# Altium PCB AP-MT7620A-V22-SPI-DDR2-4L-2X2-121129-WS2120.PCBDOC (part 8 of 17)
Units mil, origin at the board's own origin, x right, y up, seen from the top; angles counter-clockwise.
Board outline 7316 x 4279 mil, 4 copper layers (Top, Inner Layer 2, Inner Layer 3, Bottom), stack 35.4 mil thick; 640 components, 473 nets, 2041 pads, 2358 vias.
Unrouted connection lines stored in the file: 11.
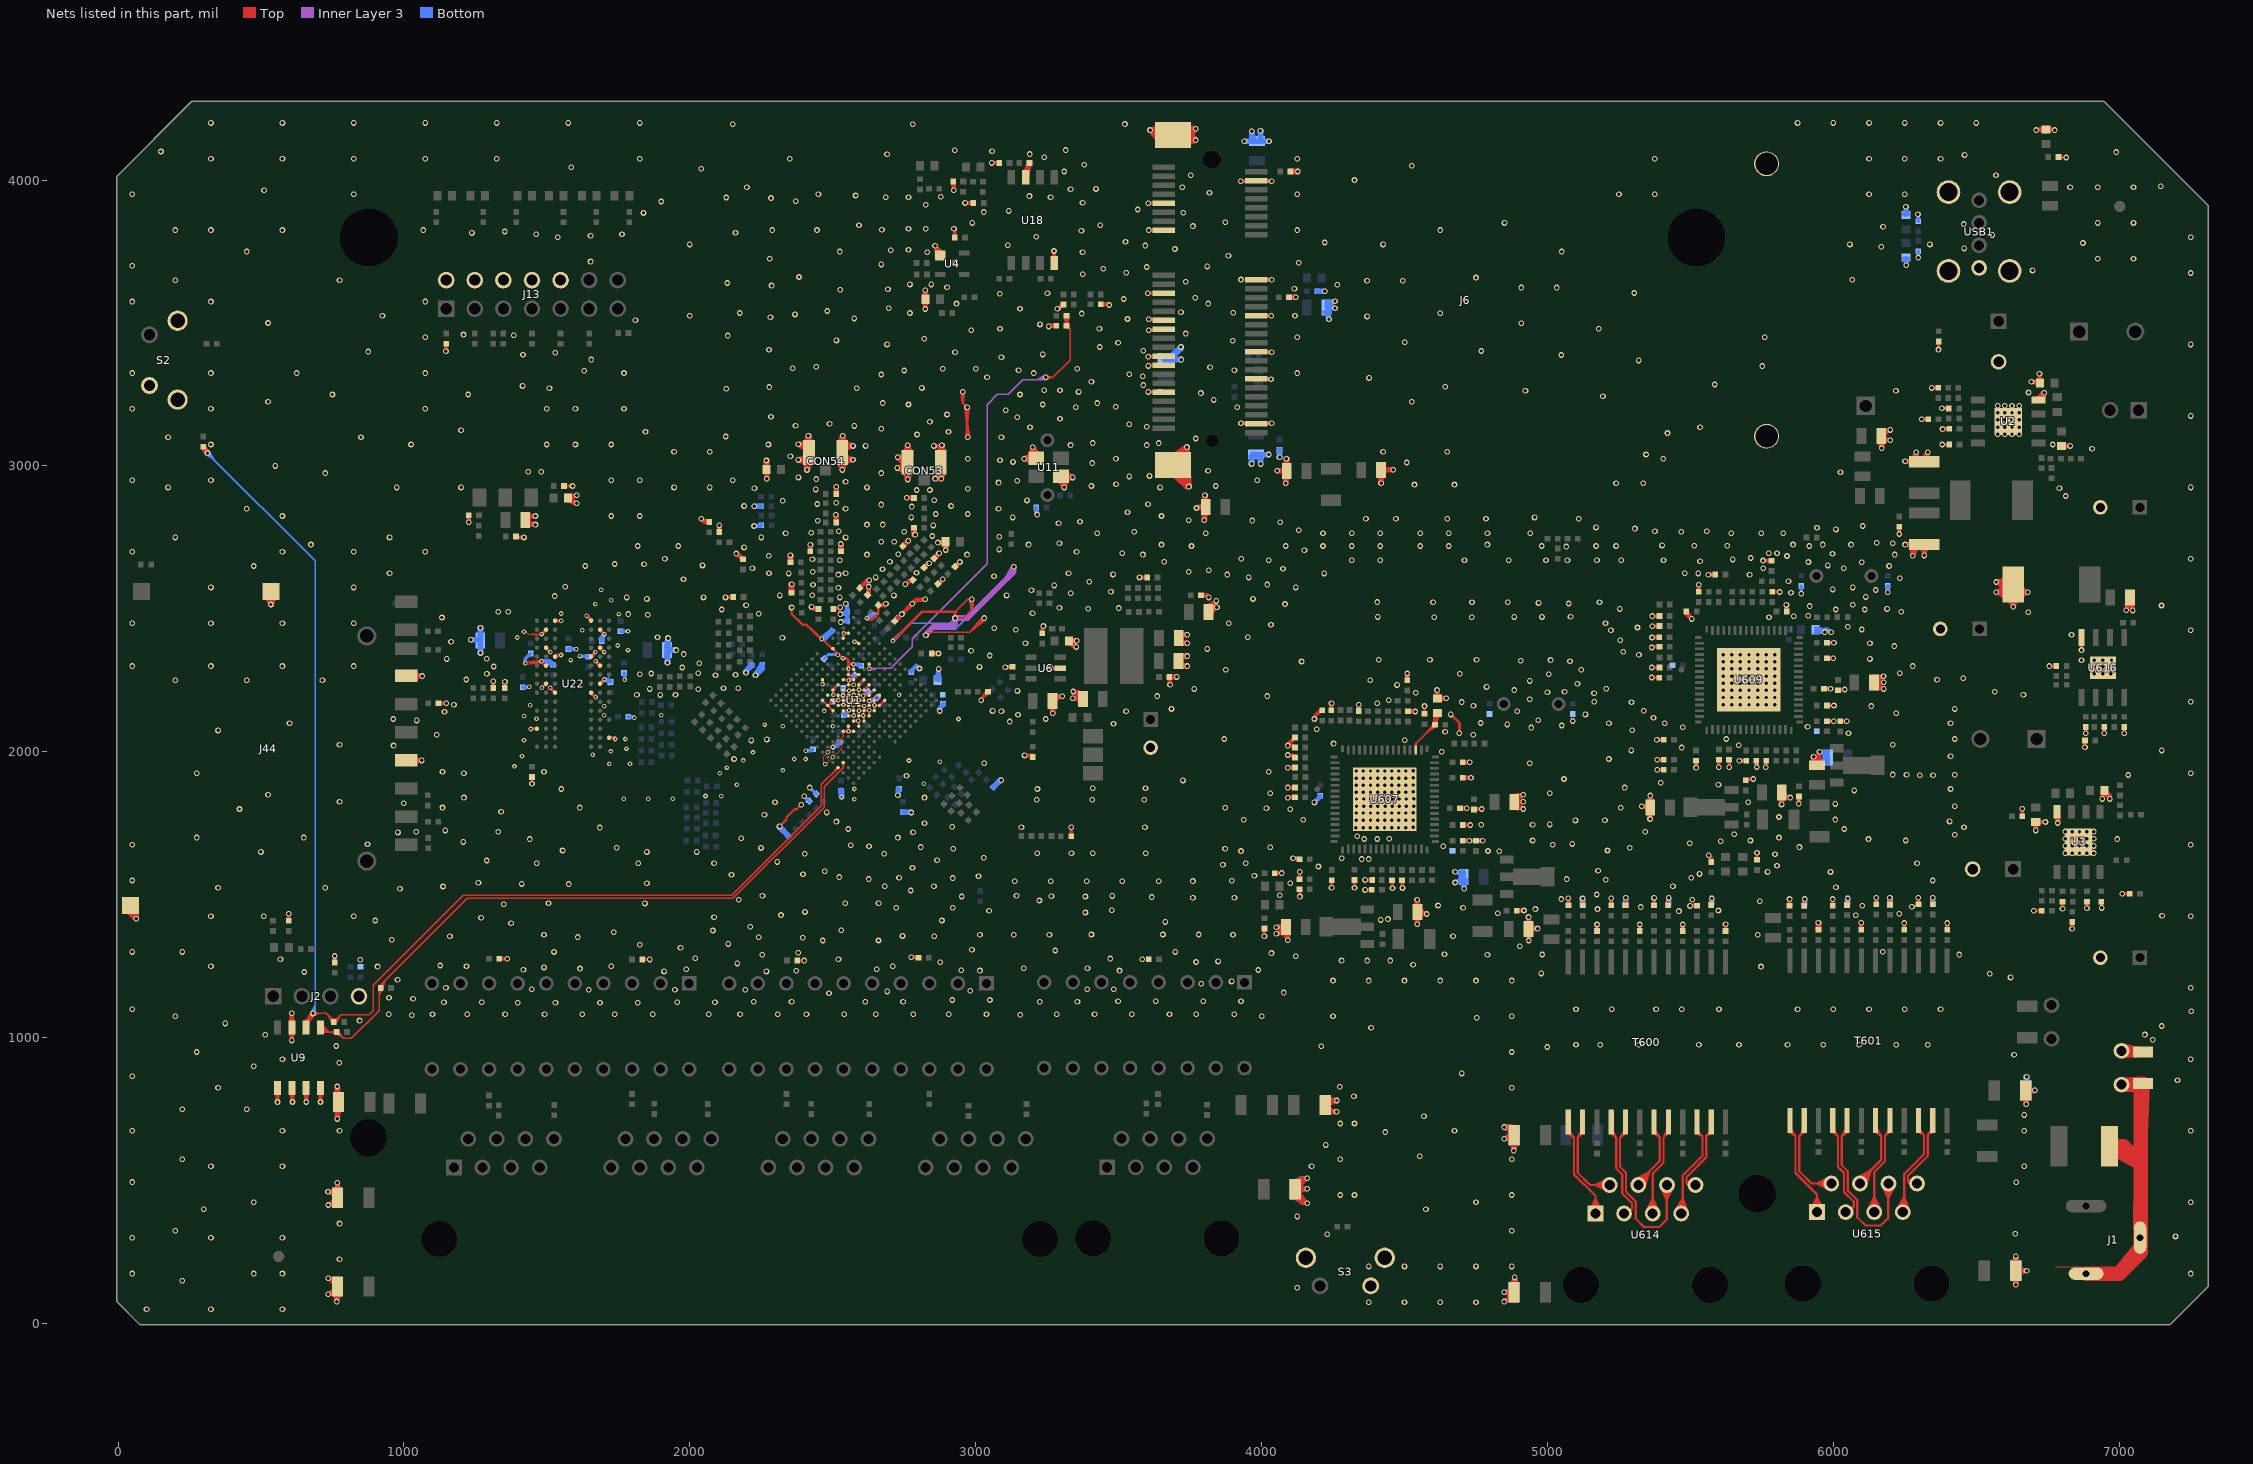
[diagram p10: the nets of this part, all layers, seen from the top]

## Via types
v1: diameter 20, hole 12, Top to Bottom, 2117 vias
v2: diameter 16, hole 8, Top to Bottom, 241 vias

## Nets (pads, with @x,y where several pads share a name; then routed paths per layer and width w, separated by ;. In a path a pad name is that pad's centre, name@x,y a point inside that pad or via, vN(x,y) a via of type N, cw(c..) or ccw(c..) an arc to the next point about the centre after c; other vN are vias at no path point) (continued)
GND: (continued)
  Inner Layer 3 w20: v1(2826,2408) 2824.14,2409.86 2854.28,2440 2920,2440 2928,2448 v1(2928,2468) 2971.59,2468 3111.59,2608 3112.1,2608 ; 3112.1,2608 3133,2628.9 v1(3133,2647) 3112.1,2608
  Bottom w5: v2@2706.28,2392.05 2754.61,2432.61 v2@2714.05,2384.28 ; v2(2710,2388) 2772,2450 2910,2450 v1(2928,2468) ; v1(2826,2408) 2846,2428 2928.14,2428 2986,2485.86 ; v1@2978.52,2533.42 2986,2485.86 ; v1@2993.48,2533.42 2986,2485.86 ; 2986,2485.86 v1(2986,2534) 2986,2485.86
  Bottom w8: C70.2@2531.04,2222.28 v2@2537,2198 ; C43.2@2535.44,2132.83 v2(2557,2145) ; v2(2536,2197) v2@2537,2198 ; C70.2@2537,2223 v2@2537,2198 ; C70.2@2542.96,2222.28 v2@2537,2198 ; C43.2@2543.62,2124.17 v2(2557,2145) ; v2(2555.5,2250.9) v2@2560.24,2250.9 ; C44.2@2571.39,2271.71 v2@2560.24,2250.9 ; C44.2@2580.12,2263.63 v2@2560.24,2250.9 ; v2(2557,2145) 2540,2128 C43.2@2539,2128 v2(2557,2145) ; v2@2560.24,2250.9 2576.27,2266.93 C44.2@2576.27,2268.23 v2@2560.24,2250.9
  Bottom w10: C75.2@2469.77,2325.23 2484.54,2340 v2(2518,2340) ; v2(2607,2196) 2608.26,2196 C40.2@2623.45,2211.19
  Bottom w12: C131.2@1416,2226 1436,2226 v2(1438,2228) ; v2(1425,2310) 1425,2325 C140.2@1444,2344 ; C138.2@1758,2422 v2(1784,2422) ; C132.2@1785,2123 1804,2123 v2(1806,2119) ; v2(2620,2468) v2@2620,2469 ; C36.2@2725.73,2466.73 2726.23,2466.23 v1(2742,2482) ; v1(2803.5,2291.5) 2792.19,2302.81 ; C42.2@2859.27,2254.17 v1(2871,2290) ; C42.2@2867.09,2250.5 2871,2250.5 v1(2871,2290) ; C42.2@2867.09,2252.5 v1(2871,2290) ; C42.2@2875.09,2252.52 v1(2871,2290) ; C118.1@4108.7,444.32 4142.5,421.7 ; C118.1@4113.51,498.63 v1(4160,508) ; C118.1@4118.12,454.25 4142.5,421.7 ; C118.1@4126.22,474.72 v1(4160,508) ; C118.1@4130.3,460.5 4142.5,421.7 ; v1(4160,421) 4159.3,421.7 4142.5,421.7 ; C229.2@4217.5,3539.3 v1(4236,3513) ; C229.2@4225.82,3576.88 v1(4257,3576) ; C229.2@4227.45,3544 v1(4236,3513) ; C229.2@4227.45,3566 v1(4257,3576) ; C229.2@4229.73,3544.24 v1@4254,3555 ; C229.2@4229.73,3565.76 v1@4254,3555 ; C229.2@4232.76,3556.37 v1(4257,3576) ; C229.2@4238.4,3545.07 v1(4236,3513) ; v1(4257,3552) v1@4254,3555 ; C797.2@4702.64,1561.9 v1(4677,1543) ; C797.2@4703.25,1563.92 v1(4677,1581) ; C797.2@4707.54,1552.05 v1(4677,1543) ; C797.2@4707.54,1563.05 C797.2@4708.27,1563.78 ; C797.2@4707.54,1574.05 v1(4677,1581) ; C797.2@4708.06,1585.04 v1(4677,1581) ; C797.2@4708.8,1541.12 v1(4677,1543) ; C810.1@4869.65,129.25 v1(4885.3,161.6) ; C817.1@4870.05,640.66 v1(4882.6,605.4) ; C810.1@4874.58,105.13 v1(4849,77) ; C817.1@4876.72,670.41 v1(4848.8,646.4) ; C810.1@4880.12,96.6 v1(4849,110) ; C810.1@4880.12,123.4 v1(4849,110) ; C810.1@4882.88,94.25 v1(4849,77) ; C810.1@4882.88,125.75 v1(4885.3,161.6) ; C817.1@4883.56,642.81 v1(4882.6,605.4) ; C817.1@4883.56,658.56 v1(4848.8,646.4) ; C817.1@4885.6,645.03 v1(4848.8,646.4) ; C810.1@4886.8,81.14 v1(4849,77) ; C810.1@4896.46,127.44 v1(4885.3,161.6) ; C817.1@4896.95,639.97 v1(4882.6,605.4) ; v1(5888,2553) C804.2@5888,2580 ; RC3.2@5937.1,2417.02 v1(5970,2419) ; RC3.2@5937.59,2425 v1(5970,2419) ; RC3.2@5938.65,2419.07 v1@5967.69,2427 ; RC3.2@5938.65,2434.93 v1@5967.69,2427 ; RC3.2@5939.99,2432.63 v1(5970,2419) ; C799.2@5976.82,1982.11 v1(5952,2000) ; C799.2@5981.54,1981.05 5981.54,1990.96 5972.5,2000 v1(5952,2000) ; C799.2@5981.54,1992.05 v1(5952,2000) ; C799.2@5982.44,2003.01 v1(5952,2000) ; v1(5992,2418) 5980.69,2429.31 5970,2429.31 v1@5967.69,2427 ; D3.1@6246.07,3878.68 v1(6254,3907) ; D4.1@6246.14,3726.9 v1(6255,3702) ; D3.1@6254,3877.59 v1(6254,3907) ; D4.1@6261.95,3727.5 v1(6255,3702) ; D3.1@6261.93,3878.68 v1(6254,3907) ; v1(6296,3880) 6297,3879 UC1.2@6297,3856 ; v1(6297,3729) UC2.2@6297,3751 ; C729.1@6624.71,203.49 v1@6638.12,234.88 ; C729.1@6624.73,166.43 v1@6638.12,136.12 ; C729.1@6638.12,169.25 v1@6638.12,136.12 ; C729.1@6638.12,200.75 v1@6638.12,234.88 ; C729.1@6640.59,171.54 v1(6676,185) ; C729.1@6640.59,198.46 v1(6676,185) ; C729.1@6651.51,166.43 v1@6638.12,136.12 ; C729.1@6651.53,203.49 v1@6638.12,234.88 ; v2@2620,2469 2629,2478 ; v2@2620,2469 C94.2@2645,2478 ; 2629,2478 C94.2@2645,2478 ; 2629,2478 C94.2@2645,2478 ; 2792.19,2302.81 2771.19,2281.81 2775,2281.81 C210.2@2775,2278 2792.19,2302.81 ; v1(3604,3259) v1@3605,3260 ; v1(3604,3259) C222.2@3645,3260 ; v1(3604,3259) C222.2@3645,3260 ; v1@3605,3260 C222.2@3645,3260 ; v1@3605,3260 C222.2@3645,3260 ; C118.1@4118.12,470 C118.1@4122.7,470 ; C118.1@4118.12,470 v1@4158.4,470 ; C118.1@4118.12,470 v1(4160,471.6) ; C118.1@4118.12,485.75 4134.4,508 ; C118.1@4118.12,485.75 v1(4160,508) ; C118.1@4118.12,485.75 4134.4,508 ; C118.1@4122.7,470 v1@4158.4,470 ; C118.1@4122.7,470 C118.1@4122.7,474.5 ; C118.1@4122.7,470 v1(4160,471.6) ; C118.1@4122.7,474.5 4122.7,441.5 4142.5,421.7 ; C118.1@4122.7,474.5 4122.7,496.3 4134.4,508 ; 4134.4,508 v1(4160,508) ; 4134.4,508 4109.42,496.32 4134.4,508 ; 4134.4,508 4130.82,480.66 4134.4,508 ; v1@4158.4,470 v1(4160,471.6) ; v1@4158.4,470 4120.44,483.49 v1(4160,471.6) ; v1@4158.4,470 4120.44,456.51 v1(4160,471.6) ; C229.2@4227.45,3555 4233.45,3549 4236,3549 v1(4236,3513) ; C229.2@4227.45,3555 v1@4254,3555 ; C229.2@4227.45,3555 4227,3555.45 4227,3567 4236,3576 v1(4257,3576) ; v1(4677,1543) 4705,1543 4705,1552.2 4705,1563 C797.2@4708.27,1563.78 ; v1(4677,1581) 4708.5,1581 4708.5,1564.01 C797.2@4708.27,1563.78 ; v1(4848.8,646.4) 4882.6,646.4 v1(4882.6,605.4) ; v1(4849,77) 4880.5,108.5 C810.1@4880.5,110 ; v1(4849,110) C810.1@4880.5,110 ; v1(4849,110) C810.1@4882.88,110 ; C810.1@4880.5,110 C810.1@4882.88,110 ; C810.1@4882.88,110 4885.3,112.42 v1(4885.3,161.6) ; v1@5967.69,2427 RC3.2@5937.59,2427 5937.59,2419 v1(5970,2419) ; v1(6255,3702) 6255,3727.41 D4.1@6254,3728.41 v1(6255,3702) ; v1@6638.12,136.12 C729.1@6638.12,185 ; v1@6638.12,136.12 v1(6638,136) C729.1@6638.12,185 ; C729.1@6638.12,185 v1(6676,185) ; C729.1@6638.12,185 v1@6638.12,234.88 ; C729.1@6638.12,185 v1(6676,185) ; C729.1@6638.12,185 v1(6638,235) v1@6638.12,234.88 ; v2(1615,2335) 1643,2335 C135.2@1645,2333 v2(1615,2335) ; C139.2@1770,2276 1772,2274 v2(1772,2252) C139.2@1770,2276 ; v1(2400,1845) C57.2@2417.27,1827.73 v1(2400,1845) ; v2(2406,2004) 2426,2004 C76.2@2431,2009 v2(2406,2004) ; v1(2420,1875) C58.2@2442.27,1852.73 v1(2420,1875) ; v2(2572.5,2306.5) 2594.2,2306.5 C91.2@2599.9,2300.8 v2(2572.5,2306.5)
  Bottom w15: C128.2@1576,2360 1602,2360 v2(1603,2359) ; v2(2500.5,2017) v2@2502.71,2014.79 ; v1(2528,2454) v1@2528,2457.52 ; v1(2546,2518) v1@2549.67,2518 ; v1(2728,1848) v1@2727.79,1848 ; v1(2874.16,2142.97) v1@2869.68,2147.45 ; C108.2@3212,2855 3212,2830 v1(3215,2830) ; C797.2@4698.21,1550.26 v1(4708.6,1521.4) ; C797.2@4705,1552.2 4708.6,1548.6 v1(4708.6,1521.4) ; C797.2@4707.54,1552.05 v1(4708.6,1521.4) ; C797.2@4716.97,1550.9 v1(4708.6,1521.4) ; v1(5931,1983) 5948.4,1965.6 ; C799.2@5978.95,1979.19 5948.4,1965.6 ; C799.2@5981.46,1960.55 5948.4,1965.6 ; C799.2@5981.54,1970.05 5948.4,1965.6 ; C799.2@5981.54,1990.96 C799.2@5981.54,1981.05 5981.54,1969.14 5978,1965.6 5948.4,1965.6 ; v1(6190,2558) C803.2@6190,2580 ; v2@2502.71,2014.79 2522.96,2035.04 2524,2035.04 C41.2@2524,2034 v2@2502.71,2014.79 ; v1@2528,2457.52 2550.9,2457.52 C103.2@2550.9,2458.7 ; v1@2528,2457.52 C103.2@2550.9,2458.7 ; v1@2549.67,2518 2549.67,2488.7 C97.2@2550.9,2488.7 ; v1@2549.67,2518 C97.2@2550.9,2488.7 ; C103.2@2550.9,2458.7 C97.2@2550.9,2488.7 ; C103.2@2550.9,2458.7 C97.2@2550.9,2488.7 ; C97.2@2550.9,2488.7 2544.2,2482 v1(2526,2482) C97.2@2550.9,2488.7 ; v1@2727.79,1848 2727.79,1871 C167.2@2733,1871 v1@2727.79,1848 ; v1@2869.68,2147.45 2888.11,2165.89 2888.11,2168 C69.1@2886,2168 v1@2869.68,2147.45 ; v2(1481,2317) 1510,2317 1521,2306 C133.2@1521,2305 v2(1481,2317) ; C130.2@1692,2388 1692,2400 v2(1701.5,2412) C130.2@1692,2388 ; v2(1700.5,2253) 1715,2253 1723,2245 C129.2@1723,2244 v2(1700.5,2253) ; v1(2225,2790) 2248,2790 R130.1@2250,2793 v1(2225,2790) ; v2(2628,2178) 2643.54,2178 C39.2@2655.27,2189.73 v2(2628,2178) ; v1(4185,1823) 4205,1843 C768.2@4205,1846 v1(4185,1823)
  Bottom w20: C73.2@1267.55,2379 v1@1267.55,2350 ; C73.2@1267.55,2401 v1(1268,2434) 1268,2390.45 C73.2@1267.55,2390 ; C136.2@1920.45,2345 v1(1922,2312) 1922,2354.45 C136.2@1920.45,2356 ; C136.2@1920.45,2367 v1(1924,2398) 1924,2359.55 C136.2@1920.45,2356 ; v1(1952,2356) C136.2@1920.45,2356 ; v1(2196.56,2276.65) v1@2193.6,2279.6 ; v1(2225.5,2859.5) R131.1@2249,2859.5 ; v1(2314,1739) v1@2312.77,1737.77 ; R42.1@2529,1864 v2(2531,1842) 2531,1862 R42.1@2529,1865 ; C166.2@2746,1789 2774.25,1789 v1(2774.25,1787.8) ; C455.1@3062.73,1877.27 3087.73,1902.27 v1(3089,1901) ; C232.2@3664,3377.45 3664,3376 3660,3372 v1(3719,3372) ; C230.2@3969,3040.55 v1(3965,3007) 3965,3035 3974.45,3035 C230.2@3978.22,3038.78 ; C230.2@3980,3040.55 C230.2@3978.22,3038.78 ; v1(4063,3030) C223.2@4063,3056 ; C228.2@4194.4,3611 v1(4221.2,3610.8) ; C817.1@4883.56,658.56 4883.56,677.44 4873.6,687.4 v1(4849.3,687.4) C817.1@4883.56,674.31 ; C812.2@6198,1466 v1(6198,1490) ; C813.2@6348,1467 v1(6348,1490) ; C814.1@6673.12,830.75 v1(6676,864) ; v1(6705,816) 6704,815 C814.1@6673.12,815 C814.1@6675,813.12 ; v1@1267.55,2350 v1(1268,2346) C73.2@1267.55,2390 ; v1@1267.55,2350 C73.2@1267.55,2390 ; C73.2@1267.55,2390 1265.55,2392 v1(1234,2392) C73.2@1267.55,2390 ; v1@2193.6,2279.6 C821.2@2217,2303 v1@2193.6,2279.6 ; 2253,2290.75 R813.2@2253,2305 ; 2253,2290.75 v1(2229.91,2267.66) R813.2@2253,2305 ; 2253,2290.75 R813.2@2253,2305 ; 2253,2290.75 R813.2@2253,2305 ; v1@2312.77,1737.77 C215.2@2345.27,1705.27 v1@2312.77,1737.77 ; v2(2462,2396) 2470.54,2396 ; v2(2462,2396) C93.2@2497.27,2422.73 ; v2(2462,2396) C93.2@2497.27,2422.73 ; 2470.54,2396 C93.2@2497.27,2422.73 ; 2470.54,2396 C93.2@2497.27,2422.73 ; C232.2@3675,3377.45 v1(3719,3372) ; C232.2@3675,3377.45 v1@3718,3411 ; C232.2@3675,3377.45 v1(3719,3372) ; C232.2@3675,3377.45 v1(3718,3416) ; C232.2@3679,3372 v1@3718,3411 ; C232.2@3679,3372 v1(3719,3372) ; C232.2@3679,3372 v1(3718,3416) ; v1@3718,3411 v1(3718,3416) ; C231.2@3966,4136 v1(3966,4171) 3973,4136.45 v1(3940,4136) C231.2@3966,4136 ; C231.2@3966,4136 C231.2@3996,4136 ; C230.2@3978.22,3038.78 v1@4023.78,3038.78 ; C230.2@3978.22,3038.78 3997,3038.78 v1(3997,3007) 3991,3040.55 v1@4023.78,3038.78 ; C230.2@3978.22,3038.78 v1(4025,3040) v1@4023.78,3038.78 ; C231.2@3996,4136 v1(3996,4173) 3995,4136.45 v1(4026,4136) C231.2@3996,4136 ; v1(6675,767) C814.1@6675,813.12 ; v1(6675,767) C814.1@6675,809.5 ; v1(6675,767) 6673.12,799.25 v1(6675,767) ; C814.1@6675,809.5 C814.1@6676,810.5 ; C814.1@6675,809.5 C814.1@6675,813.12 ; C814.1@6676,810.5 v1(6676,864) ; C814.1@6676,810.5 v1(6676,864) ; C806.2@5123.05,1463 v1(5123,1487) C806.2@5123.05,1463 C806.2@5123.05,1463 ; C807.2@5273.05,1463 5274,1463.95 v1(5274,1490) C807.2@5273.05,1463 ; C808.2@5423.05,1463 5424,1463.95 v1(5424,1489) C808.2@5423.05,1463 ; C809.2@5573,1464 5575,1466 v1(5575,1487) C809.2@5573,1464 ; C811.2@5898,1462 5900,1464 v1(5900,1485) C811.2@5898,1462 ; C815.2@6048,1464 6050.1,1466.1 v1(6050.1,1487) C815.2@6048,1464
  other v1: 100,50 325,50 575,50 4375,75 4500,75 4625,75 4750,75 4125,125 225,150 50,175 475,175 575,175 7250,175 4375,200 4500,200 4625,200 4750,200 4875,200 775,225 50,300 325,300 575,300 7197,305 4229.5,312.5 6636,314 200,325 4875,325 775,350 4125,375 300,400 4575,400 475,425 4750,425 7250,425 4275,450 4325,450 4875,450 6640,494 50,495 325,550 575,550 4175,550 6668,550 225,575 4275,575 4875,575 4553,585 4225,625 4433,670 50,675 575,675 775,675 4675,675 6668,675 7250,675 4275,700 4325,700 4568,725 6668,730 225,750 450,750 4323,795 350,825 4875,825 4274,829 7204,851 50,865 4700,875 475,900 774,912 575,925 7250,925 6632.12,940.8 275,950 4875,950 4999.16,967.68 4209,970 763,971 5100,975 5185,975 5320,975 5530,975 5670,975 5840,975 5965,975 6090,975 6220,975 6330,975 7117,993 515,1010 7090,1011 4383,1035 7149,1041 375,1050 845,1060 4753,1070 200,1075 4001,1075 4250,1075 4875,1075 1027,1079 3156,1080 947,1082 1100,1082 1222,1082 1354,1082 1492,1082 1624,1082 1738,1082 1870,1082 2066,1082 2176,1082 2308,1082 2408,1082 2540,1082 2650,1082 2782,1082 2906,1082 3038,1082 3284,1082 3416,1082 3546,1082 3678,1082 3772,1082 3904,1082 7252,1093 50,1100 5100,1100 5225,1100 5380,1100 5470,1100 5600,1100 5875,1100 6000,1100 6125,1100 6250,1100 6375,1100 1398,1122 1530,1122 1686,1122 1818,1122 1140,1124 1272,1124 1956,1124 2088,1124 2224,1126 2356,1126 2614,1126 2746,1126 3224,1126 3356,1126 3498,1128 3630,1128 3796,1128 3928,1128 2918,1132 3050,1132 1032,1136 948,1140 2487,1156 4078,1158 2691,1162 2981,1164 1647,1168 1948,1168 2194,1168 1447,1170 3390,1170 3483,1170 1147,1175 7250,1175 3789,1189 3895,1197 4250,1200 4375,1200 4500,1200 4625,1200 4750,1200 4875,1200 978,1203 6620,1211 6547,1224 4978,1225 651,1230 1910,1232 2268,1232 2372,1234 3015,1235 3503,1235 2950,1236 3988,1237 1418,1238 1988,1240 2654,1240 1616,1242 3168,1243 3391,1243 1490,1246 908,1249 5747,1249 325,1250 1219,1250 1725,1250 2710,1250 1127.64,1252.58 4530,1255 2166,1260 2876,1264 3771,1265 3848,1267 4280,1270 4370,1270 4450,1270 847,1273 568,1275 2520,1275 3583,1275 3471,1277 2019,1278 4120,1285 2253,1290 4790,1290 4982.05,1291.01 6440,1291 4640,1292 4034.5,1296 2379,1297 50,1300 225,1300 1525,1300 3698,1300 6173.05,1301.01 3278,1305 2987,1308 1967.88,1314.82 4903,1320 1825,1325 2135,1328 2465,1340 2660,1340 958,1343 2395,1350 2241,1351 1608,1352 1161,1355 2855,1355 4670,1355 2744,1356 1490,1360 3015,1360 3133,1360 3258,1360 3900,1360 5736,1360 3405,1361 3655,1361 3780,1361 1734.48,1369.28 2081,1375 2530,1376 2212,1388 1375,1400 3663,1405 900,1410 2882,1410 4417,1412 4442,1415 1270,1420 2085.03,1421.53 325,1425 510,1425 825,1425 7250,1425 7150,1427 6078.55,1428.01 2319,1429 6231,1433.6 4825.99,1435.05 3384,1438 2403,1440 5460,1443 3047,1444 5598,1445 3476,1446 4958,1450 5175,1450 2722.54,1454.86 2920,1455 4705,1455 5326.05,1457.01 6275.05,1458.01 6101.05,1462.01 4617.4,1462.6 1349,1467 1505.7,1469.97 1843.2,1469.79 2544,1470 2660.3,1470.42 5743,1477 3223,1480 2171,1483 5507,1483 5048,1485 3760,1490 3905,1490 3616,1492 2951,1494 3384,1494 3265,1495 3478,1496 2254,1497 3143,1497 4064,1498 5172.05,1501.01 2773,1515 986,1521 350,1525 725,1525 6009,1526 1137,1529 2682,1530 2854,1530 5439,1530 1412,1538 1576.91,1537.56 1850,1540 4100,1540 1260.82,1542.57 3262.98,1547.44 3388.06,1547.44 3513.06,1547.43 3640.02,1547.31 3136.41,1547.8 3760,1548 3896,1549 50,1550 6348,1550 5203.55,1552.51 2626,1555 5068,1555 2919.5,1558.5 2732,1560 5503,1560 2523,1562 3010,1565 3975,1567 2146,1570 2396,1572 5532,1573 5770,1580 5990,1580 2472,1582 5177.05,1584.01 2779,1595 4199,1599 5802.9,1601.3 3865,1605 1465,1610 1820,1610 2085,1610 3945,1610 6293,1610 2306,1615 1290,1620 2865,1621 4350,1625 4375,1625 4281,1628 3028,1630 5796,1642 2402,1644 2680,1644 3215,1645 3335,1645 3410,1645 3595,1645 6811,1646 6836,1646 6861,1646 6886,1646 6911,1646 500,1650 1850,1650 2024,1650 4830.99,1652.05 3928,1653 4791.99,1653.05 1555,1655 5210,1655 2922,1661 3872.36,1660.94 2249,1664 1745,1665 5288,1665 4030.79,1666.28 2808,1667 5881.5,1667 4636,1669.5 2627,1670 6811,1671 6836,1671 6861,1671 6886,1671 6911,1671 2563,1673 50,1675 5018.99,1675.05 7250,1675 872.8,1677.2 5087,1678 5498,1680 1208,1685 5606,1687 4948,1690 5710,1690 6253.5,1690 1440,1695 4358.99,1695.05 4404.99,1695.05 6123,1695 6993,1695 4447,1696 6811,1696 6836,1696 6861,1696 6886,1696 6911,1696 2180,1698 275,1700 650,1700 2728,1700 5810,1700 4335,1705 6425,1710 5653,1712 979,1718 2781,1719 1043,1720 1330,1720 5342,1720 6811,1721 6836,1721 6861,1721 6886,1721 6911,1721 1145,1725 2554,1730 6038,1730 1685,1735 4330,1735 4355,1735 4380,1735 4405,1735 4430,1735 4455,1735 4479,1735 4504,1735 3160,1736 3592,1736 4530,1736 6457,1736 2918,1738 4768,1745 4948,1745 5007.99,1746.05 2821,1750 2513,1756 6406.5,1756.5 4331,1760 4356,1760 4381,1760 4406,1760 4431,1760 4456,1760 4480,1760 4505,1760 5098,1760 4531,1761 5201,1761 3937.97,1762.67 4145.99,1762.56 6007,1763 5810,1772 2261,1780 4331,1786 4356,1786 4381,1786 4406,1786 4431,1786 4456,1786 4480,1786 4505,1786 4531,1787 2479,1788 1340,1790 4100,1799 425,1800 4017,1803 5256,1804 1135,1805 1615,1805 3873,1804.5 4332,1809 4357,1809 4382,1809 4407,1809 4432,1809 4457,1809 4481,1809 4506,1809 4532,1810 6425,1810 6007,1817.7 999,1820 2298,1824 5702,1824 775,1825 3214,1832 3408,1832 3590,1832 4332,1835 4357,1835 4382,1835 4407,1835 4432,1835 4457,1835 4481,1835 4506,1835 4532,1836 1210,1840 2821,1840 525,1850 4030,1855 5008,1855 4331,1859 4356,1859 4381,1859 4406,1859 4431,1859 4456,1859 4480,1859 4505,1859 4531,1860 6073,1865 1550,1870 3216,1870 6410,1870 3410,1873 3594,1873 5270,1875 4331,1883 4356,1883 4381,1883 4406,1883 4431,1883 4456,1883 4480,1883 4505,1883 4531,1884 5598,1885 5396,1892 3725,1900 5058,1905 4331,1908 4356,1908 4381,1908 4406,1908 4431,1908 4456,1908 4480,1908 4505,1908 4531,1909 2758,1916 6302.4,1918.3 6348.9,1917.7 6256.3,1919.5 7032,1919 6207.4,1920.4 6425,1920 275,1925 1210,1925 7250,1925 1135,1930 1490,1930 4025,1930 4331,1933 4356,1933 4381,1933 4406,1933 4431,1933 4456,1933 4480,1933 4505,1933 4531,1934 3030,1960 4938,1960 2155,1975 5215,1975 6410,1985 4630,2000 5293,2005 7149,2005 5470,2015 964,2022 5669,2023 775,2025 6208,2025 4252,2029 2215,2040 4501,2041 2269.77,2043.42 3870,2045 5625,2045 6425,2045 1115,2060 4740,2060 6053,2065 4642,2070 350,2075 5297,2076 4193,2079 4943,2085 5473,2086 5910,2087.5 5049.99,2092.05 4859,2096 3482,2098 600,2100 5215,2100 5410,2100 6410,2100 4767,2101 3119,2106 5089,2108 1045,2110 4967.99,2110.05 963,2115 3245,2115 5371,2119 3148,2130 5133,2131 6219.9,2135 1142,2140 3090,2141.5 3526,2142 4894,2142 3059,2143 5337,2144 3685,2150 6425,2150 6133,2160 4741,2161 1175,2165 5615,2165 5645,2165 5675,2165 5705,2165 5735,2165 5765,2165 5795,2165 4405,2170 5294,2173 4700,2174 5163.99,2175.05 7250,2175 4445,2180 4938,2184 5615,2190 5645,2190 5675,2190 5705,2190 5735,2190 5765,2190 5795,2190 3635,2195 4020,2195 1897,2199 1815,2200 1950,2200 6665,2200 5163,2205 4539,2207 5000,2208 5060,2210 6565,2210 3146,2213 5615,2215 5645,2215 5675,2215 5705,2215 5735,2215 5765,2215 5795,2215 4884,2216 2030,2219 1860,2220 3765,2220 5206,2221 2118,2222 2170,2222 4787,2227 4474,2234 5105,2238 5615,2240 5645,2240 5675,2240 5705,2240 5735,2240 5765,2240 5795,2240 4938,2248 200,2250 450,2250 715,2250 4380,2250 6363,2252 1218,2253 6454,2257 5615,2265 5645,2265 5675,2265 5705,2265 5735,2265 5765,2265 5795,2265 2090,2268 2160,2270 1825,2271 5005,2271 1290.5,2273.5 4693,2273 6913,2273 6943,2273 6971,2273 1865,2274 2030,2275 6232.2,2275.4 3875,2287 5118,2287 5615,2290 5645,2290 5675,2290 5705,2290 5735,2290 5765,2290 5795,2290 1974,2295 3013.5,2297 6913,2297 6943,2297 6972,2297 1314.5,2298.5 50,2300 325,2300 575,2300 825,2300 6278,2300 2033,2310 5615,2315 5645,2315 5675,2315 5705,2315 5735,2315 5765,2315 5795,2315 4140,2316 5079,2317 4907,2319 6868,2320 6913,2320 6943,2320 6973,2320 5011,2321 4410,2322 4589,2322 4752,2322 1150,2325 6128,2325 1290,2326 3049,2337 5320,2340 5615,2340 5645,2340 5675,2340 5705,2340 5735,2340 5765,2340 5795,2340 1979,2342 5265,2350 2984,2354 3810,2360 6213,2370 3174,2380 6128,2380 1165,2385 5255,2390 2324,2399 1887,2401 3952,2401 6833,2410 5222,2425 7250,2425 3140,2427 6098.99,2428.05 3065,2432 5315,2435 6050,2438 4033,2445 50,2450 325,2450 575,2450 825,2450 3885,2450 5203,2450 1133,2470 4604,2471 4735,2471 5775,2471 4406,2472 4884,2472 4981,2472 5081,2473 5862,2474 5912,2476 1853,2480 1785,2482 2241,2483 3199,2484.5 6682,2488 1330,2490 1365,2490 6238,2490 2112,2498 6008,2498 6110,2498 5253,2500 6188,2500 3394,2501 3500,2503 3293,2504 5918,2510 7148,2512 2197,2513 6068,2515 4082,2517 5075,2519 4969,2521 4600,2523 4736,2523 4861,2523 5182,2523 4405,2524 1850,2535 3970,2535 1780,2540 2048,2540 2525,2540 6113,2542 1528,2545 2315,2547 2714,2547 3108,2547 2428,2548 3333,2555 5851.99,2556.05 3473,2560 3195,2565 6148,2566 5998,2568 2520,2574 325,2575 825,2575 4120,2575 6068,2575 1564,2577 3275,2582 2431,2584 4020,2585 3397,2595 5842.99,2597.05 1978,2604 6232,2607 2650,2610 3955,2610 3064,2614 5707,2619 2520,2620 3880,2620 3480.5,2620.5 2346,2624 4219,2624 5528,2624 950,2625 2277,2625 2545,2625 3325,2625 5480,2625 2793,2626 2430,2630 3745,2630 3815,2635 2674,2639 4075,2640 2219,2642 5754.78,2641.75 6036,2642 475,2650 1634,2650 6195,2650 2044.5,2652 5980,2652 1840,2656 1738,2657 6099,2663 5913,2664 2700,2665 3660,2665 5534,2667 2525,2670 4025,2670 4315,2670 4415,2670 4710,2670 4865,2670 4995,2670 5070,2670 5173,2670 5258,2670 5406,2670 5648,2673 2429,2674 1913,2675 3929,2675 7250,2675 5711,2678 5838,2685 2276,2686 2620,2690 2970,2690 3585,2690 6215,2690 2729,2691 5997,2693 3513,2695 5774,2695 5803,2695 50,2700 575,2700 825,2700 1075,2700 3353,2700 4150,2705 3082,2708 2190,2715 5066,2718 1818,2720 1960,2720 3755,2720 4085,2720 4215,2720 4315,2720 4415,2720 4555,2720 4655,2720 4980,2720 5170,2720 5240,2720 5916,2720 5514,2721 5629,2721 5401,2722 675,2725 3185,2725 3650,2725 4790,2725 5859,2725 5963,2725 6062,2725 3293,2730 6208,2730 6152,2731 2670,2735 2715,2735 200,2750 950,2750 2250,2750 2545,2750 3082,2752 2848,2755 2335,2765 3425,2765 3805,2765 4215,2765 4315,2765 4415,2765 4555,2765 4655,2765 4790,2765 4940,2765 5643,2765 5748,2765 5825,2765 2425,2766 2750,2770 3555,2770 5468,2770 2521,2772 5376,2772 5557,2772 4130,2775 6009,2778 5306,2781 5943,2784 5170,2785 6103,2790 2852,2792 2620,2795 2675,2795 3290,2800 4065,2803 3365,2805 2448,2808 3967,2809 3745,2810 4365,2815 4470,2815 4650,2815 4785,2815 5110,2815 2775,2820 3130,2820 4955,2820 575,2825 1725,2825 1825,2825 3650,2825 2860,2832 2972,2832 3531,2838 450,2850 2545,2850 3080,2850 2776,2858 2190,2860 2914,2860 2670,2865 3603,2866 2446,2867 2512,2871 2325,2878 3179.5,2879.5 2855,2880 6813,2895 2794,2916 2840,2916 2441,2918 2972,2920 2226,2922 6791,2922 175,2925 975,2925 1200,2925 1945,2925 2070,2925 2620,2925 3645,2925 7250,2925 3405,2930 3840,2930 4535,2935 4675,2935 3491,2936 5240,2940 5335,2940 3080,2942 2545,2945 3145.5,2948.5 50,2950 325,2950 1725,2950 1825,2950 2150,2950 3985,2950 2442,2954 2380,2960 3537.5,2963.5 3608,2965 725,2975 2670,2975 6025,2978 1435,2980 1480,2980 3813,2983 550,3000 3408,3010 4508,3012 3130.5,3014 3085,3020 2972,3025 3490.5,3025 5405,3025 2352,3034 5345,3040 1945,3050 2070,3050 4425,3050 4650,3050 6905,3060 2615,3070 3332,3073 3598,3073 325,3075 1025,3075 1500,3075 1600,3075 1725,3075 2275,3075 6768,3075 3410,3080 3640,3080 3769.5,3096 175,3100 850,3100 3090,3100 2126,3103 2795,3110 6575,3111 6600,3111 6625,3111 6650,3111 5420,3115 1845,3120 2905,3120 1200,3125 2670,3130 3190,3135 5533.8,3135.3 6575,3136 6600,3136 6625,3136 6650,3136 3598,3137 2575,3140 2370,3141 3537.5,3146 2489,3148 2840,3155 6575,3161 6600,3161 6625,3161 6650,3161 3295,3165 3145,3170 2284,3172 7250,3175 2900,3180 6575,3186 6600,3186 6625,3186 6650,3186 3105,3195 50,3200 325,3200 1075,3200 1500,3200 1600,3200 1770,3200 3350,3205 3915,3205 3490,3207 6575,3211 6600,3211 6625,3211 6650,3211 2765,3215 3235,3215 2675,3220 3425,3220 525,3225 4525,3225 3833,3231 5194,3244 750,3250 1225,3250 3155,3250 3788,3255 6683,3257 3360,3259 4923,3263 6219,3263 3240,3265 3295,3265 2128,3270 1509,3272 2584,3272 2812,3273 2278,3276 4643,3277 1415,3280 3586,3283 5585,3285 3405,3295 4376,3308 3040,3310 3584,3314 2670,3320 3537.5,3321 50,3325 325,3325 625,3325 1075,3325 1770,3325 3203,3325 4125,3325 1631,3333 2750,3334 3150,3335 3905,3335 2885,3340 3000,3340 3355,3340 2360,3342 3820,3345 2442,3347 5751.4,3349.4 5319,3369 1655,3372 3090,3380 5048,3388 1416.5,3388.5 3235,3390 1529.5,3395.5 2928,3398 875,3400 4768,3402 3586,3403 2277,3406 3434,3416 2690,3425 7250,3425 3498,3431 4501,3433 3899,3438 2513,3439 2820,3445 1075,3450 4125,3450 5760,3450 2133,3456 1384.5,3457 1208.5,3459.5 3735,3463 2985,3475 3085,3480 3433,3480 5179,3480 3225,3495 4908,3499 525,3500 1810,3510 3531,3514 2575,3516 2282,3520 4369,3523 925,3525 2000,3525 4117,3525 2368,3530 3371,3533 4625,3534 2175,3535 2770,3535 3901,3536 3718,3538 2481,3542 3155,3550 2696,3552 2933,3568 3814,3568 50,3575 325,3575 1075,3575 3518,3584 3768,3588 3084,3602 3251,3604 5304,3605 2526,3616 2693,3618 4115,3620 4908,3624 5033,3624 2900,3625 2286,3631 4265,3634 2770,3635 2845,3635 2131,3640 3735,3644 4369,3648 4494,3648 200,3650 775,3650 6066,3651 3928,3652 4750,3659 2382,3661 3375,3671 7250,3675 3527,3676 6697,3684 3446,3690 3598,3696 3810,3698 50,3700 2670,3705 4130,3711 2928,3712 1653,3715 2280,3725 6925,3725 7050,3725 3884,3735 2831,3748 3374,3748 450,3750 2525,3750 5050,3750 2703,3755 2765,3756 3697,3759 6458,3761 6168,3767 3593,3771 3112,3772 2000,3775 4425,3775 6058,3775 6338,3775 6873,3780 4221,3781.6 3524,3784 1538,3800 7250,3800 3212,3802 1653,3805 6556,3808 1463,3810 1763,3810 1238,3815 2160,3816 1353,3820 3370,3823 200,3825 325,3825 575,3825 1068,3825 2288,3825 2445,3825 4125,3825 4625,3825 2672,3826 2765,3830 2825,3830 6174,3837 3760,3839 3435.5,3841.5 2592,3842 6456,3846 2988,3850 4850,3850 6925,3850 7050,3850 3873,3852 1838,3885 3726,3886 3028,3888 3116,3892 3566.5,3897 2825,3914 3374,3921 1900,3925 2371,3926 2284,3937 2128,3939 2685,3940 2765,3940 3262,3940 2878,3942 3188,3944 2580,3946 50,3950 825,3950 2450,3950 4125,3950 5250,3950 5375,3950 6125,3950 6250,3950 3818,3956 511,3964 3332,3968 3421,3969 2200,3975 3723,3975 6828,3975 6925,3975 7050,3975 7145,3978 4325,4000 3752,4017 6569,4017 3310,4030 2040,4040 1585,4045 4525,4050 3380,4054 325,4075 575,4075 825,4075 1075,4075 1325,4075 1825,4075 2350,4075 4125,4075 5375,4075 6125,4075 6250,4075 6375,4075 3240,4080 6459,4088 2690,4090 3189.5,4091 6990,4098 150,4100 3057.5,4101 2926.5,4104 3315,4105 2150,4195 2780,4195 3522,4196 325,4200 575,4200 825,4200 1075,4200 1325,4200 1575,4200 1825,4200 5875,4200 6000,4200 6125,4200 6250,4200 6375,4200 6500,4200
  other v2: 1769,1835.5 1855,1835.5 1940,1835.5 2576,1834.5 2055,1845.5 2110,1845 2576,1870 2165,1885 2818,1888 2105,1925 2325,1935 2130,1945 1387,1949 1719,1958 1791,1958 2873.95,1965.48 2187,1970 2766.86,1969.59 2365,1975 2405,1975 1413,1985 1660,1990 2221,1998 1723.9,2001.37 1778.73,2011.41 1420,2041 1775,2045 2325,2090 2500.6,2089.6 2261.54,2095.29 1463.88,2115.31 2940,2115 1421,2124 1701,2128.5 1900,2128 2470,2143 1700.95,2159.59 1442,2163 2732,2200 1584,2321 1784,2356 1748,2372 1396,2400 1624,2425 1752,2482 1550,2484 1670,2516 1725,2530 1690,2567
GND_L_5-POWER0: D1.1 J1.1 J1.2 L36.1 R257.1 | length 2275
  Top w4: 6775.5,198.96 6865,198.96 ; J1.1@6865.48,168.21 6865,198.96 ; J1.1@6869.64,168.56 6865,198.96 ; J1.1@6873.64,169.45 6865,198.96 ; J1.1@6877.44,170.84 6865,198.96 ; J1.1@6881,172.7 6865,198.96 ; J1.1@6884,174.78 6884,178.96 6884.5,179.46 6865,198.96 ; J1.1@6886.73,177.2 6865,198.96 ; J1.1@6889.38,180.22 6865,198.96 ; J1.1@6891.63,183.58 6865,198.96 ; J1.1@6893.44,187.26 6865,198.96 ; J1.1@6894.77,191.22 6865,198.96
  Top w50: J1.1@6884,174.78 7000,174.78 ; J1.1@6923.37,174.78 7000,174.78 ; R257.1@7067.25,839.88 L36.1@7008,835.94 7079.06,835.94 R257.1@7083,839.88 ; J1.2@7072.98,265.33 7000,174.78 ; J1.2@7072.98,300.76 7075,298.74 J1.2@7075,249.78 ; J1.2@7072.98,336.2 7075,507.86 ; 7075,668.03 R257.1@7083,839.88 ; D1.1@6966.58,620 7013.83,620 ; D1.1@6966.58,620 7075,558.83 ; D1.1@6966.58,620 7013.83,620 ; 7000,174.78 J1.2@7075,249.78 ; 7013.83,620 7075,558.83 ; J1.2@7075,249.78 7075,558.83 ; 7075,558.83 7075,831.88 R257.1@7083,839.88
GP1_GE_2_4-ETHERNET: T601.13 U615.1 | length 756.7
  Top w8: T601.13@5844.69,672.46 5868.05,655.01 ; T601.13@5848.05,676.23 5868.05,655.01 ; T601.13@5848.05,710.48 5848.05,675.01 5868.05,655.01 ; T601.13@5852.02,679.37 5868.05,655.01 ; U615.1@5920.11,395.39 5943.05,441.57 ; U615.1@5927.67,392.36 5943.05,441.57 ; U615.1@5935.51,390.56 5943.05,441.57 ; U615.1@5943.05,390.01 5943.05,452.01 5868.05,527.01 5868.05,655.01 ; U615.1@5950.59,390.56 5943.05,441.57 ; U615.1@5958.43,392.36 5943.05,441.57 ; U615.1@5965.99,395.39 5943.05,441.57
GP1_GE_4-ETHERNET: T600.13 U614.1 | length 756.7
  Top w8: T600.13@5069.69,667.46 5093.05,650.01 ; T600.13@5073.05,671.23 5093.05,650.01 ; T600.13@5073.05,705.48 5073.05,670.01 5093.05,650.01 ; T600.13@5077.02,674.37 5093.05,650.01 ; U614.1@5145.11,390.39 5168.05,436.57 ; U614.1@5152.67,387.36 5168.05,436.57 ; U614.1@5160.51,385.56 5168.05,436.57 ; U614.1@5168.05,385.01 5168.05,447.01 5093.05,522.01 5093.05,650.01 ; U614.1@5175.59,385.56 5168.05,436.57 ; U614.1@5183.43,387.36 5168.05,436.57 ; U614.1@5190.99,390.39 5168.05,436.57
GP2_GE_2_4-ETHERNET: T601.14 U615.2 | length 754.5
  Top w8: T601.14@5893.89,679.1 5881.05,656.01 ; T601.14@5898.05,676.23 5881.05,656.01 ; T601.14@5898.05,710.48 5898.05,673.01 5881.05,656.01 ; T601.14@5901.59,672.62 5881.05,656.01 ; U615.2@5987.67,467.07 5941.49,490.01 ; U615.2@5987.67,512.95 5941.49,490.01 ; U615.2@5990.7,474.63 5941.49,490.01 ; U615.2@5990.7,505.39 5941.49,490.01 ; U615.2@5992.5,482.47 5941.49,490.01 ; U615.2@5992.5,497.55 5941.49,490.01 ; 5881.05,656.01 5881.05,533.01 5924.05,490.01 U615.2@5993.05,490.01 5941.49,490.01
GP2_GE_4-ETHERNET: T600.14 U614.2 | length 754.5
  Top w8: T600.14@5118.89,674.1 5106.05,651.01 ; T600.14@5123.05,671.23 5106.05,651.01 ; T600.14@5123.05,705.48 5123.05,668.01 5106.05,651.01 ; T600.14@5126.59,667.62 5106.05,651.01 ; U614.2@5212.67,462.07 5166.49,485.01 ; U614.2@5212.67,507.95 5166.49,485.01 ; U614.2@5215.7,469.63 5166.49,485.01 ; U614.2@5215.7,500.39 5166.49,485.01 ; U614.2@5217.5,477.47 5166.49,485.01 ; U614.2@5217.5,492.55 5166.49,485.01 ; 5106.05,651.01 5106.05,528.01 5149.05,485.01 U614.2@5218.05,485.01 5166.49,485.01
GP3_GE_2_4-ETHERNET: T601.16 U615.3 | length 454.5
  Top w8: T601.16@5994.42,672.71 6016.05,654.01 ; T601.16@5998.05,676.23 6016.05,654.01 ; T601.16@5998.05,710.48 5998.05,672.01 6016.05,654.01 ; T601.16@6002.24,679.05 6016.05,654.01 ; U615.3@6043.05,390.01 6044.05,391.01 6055.05,391.01 6071.05,407.01 6071.05,426.01 6037.05,460.01 6037.05,527.01 6016.05,548.01 6016.05,654.01
GP3_GE_4-ETHERNET: T600.16 U614.3 | length 454.5
  Top w8: T600.16@5219.42,667.71 5241.05,649.01 ; T600.16@5223.05,671.23 5241.05,649.01 ; T600.16@5223.05,705.48 5223.05,667.01 5241.05,649.01 ; T600.16@5227.24,674.05 5241.05,649.01 ; U614.3@5268.05,385.01 5269.05,386.01 5280.05,386.01 5296.05,402.01 5296.05,421.01 5262.05,455.01 5262.05,522.01 5241.05,543.01 5241.05,649.01
GP4_GE_2_4-ETHERNET: T601.19 U615.4 | length 776.5
  Top w8: U615.4@6077.94,508.08 6131.8,537.76 ; U615.4@6082.31,501.26 6131.8,537.76 ; U615.4@6087.48,495.12 6131.8,537.76 ; U615.4@6099.2,485.62 6131.8,537.76 ; U615.4@6106.27,481.81 6131.8,537.76 ; U615.4@6113.85,478.94 6131.8,537.76 ; T601.19@6144.79,672.37 6168.05,656.01 ; T601.19@6148.05,676.23 6168.05,656.01 ; T601.19@6148.05,710.48 6148.05,676.01 6168.05,656.01 ; T601.19@6151.95,679.45 6168.05,656.01 ; 6131.8,537.76 U615.4@6093.05,490.01 6093.05,497.01 6092.05,498.01 6168.05,574.01 6168.05,656.01
GP4_GE_4-ETHERNET: T600.19 U614.4 | length 776.5
  Top w8: U614.4@5302.94,503.08 5356.8,532.76 ; U614.4@5307.31,496.26 5356.8,532.76 ; U614.4@5312.48,490.12 5356.8,532.76 ; U614.4@5324.2,480.62 5356.8,532.76 ; U614.4@5331.27,476.81 5356.8,532.76 ; U614.4@5338.85,473.94 5356.8,532.76 ; T600.19@5369.79,667.37 5393.05,651.01 ; T600.19@5373.05,671.23 5393.05,651.01 ; T600.19@5373.05,705.48 5373.05,671.01 5393.05,651.01 ; T600.19@5376.95,674.45 5393.05,651.01 ; 5356.8,532.76 U614.4@5318.05,485.01 5318.05,492.01 5317.05,493.01 5393.05,569.01 5393.05,651.01
GP5_GE_2_4-ETHERNET: T601.20 U615.5 | length 729.6
  Top w8: U615.5@6120.11,395.39 6143.05,441.57 ; U615.5@6127.67,392.36 6143.05,441.57 ; U615.5@6135.51,390.56 6143.05,441.57 ; U615.5@6143.05,390.01 6143.05,530.01 6181.05,568.01 6181.05,657.01 ; U615.5@6150.59,390.56 6143.05,441.57 ; U615.5@6158.43,392.36 6143.05,441.57 ; U615.5@6165.99,395.39 6143.05,441.57 ; T601.20@6193.95,679.19 6181.05,657.01 ; T601.20@6198.05,676.23 6181.05,657.01 ; T601.20@6198.05,710.48 6198.05,674.01 6181.05,657.01 ; T601.20@6201.49,672.52 6181.05,657.01
GP5_GE_4-ETHERNET: T600.20 U614.5 | length 729.6
  Top w8: U614.5@5345.11,390.39 5368.05,436.57 ; U614.5@5352.67,387.36 5368.05,436.57 ; U614.5@5360.51,385.56 5368.05,436.57 ; U614.5@5368.05,385.01 5368.05,525.01 5406.05,563.01 5406.05,652.01 ; U614.5@5375.59,385.56 5368.05,436.57 ; U614.5@5383.43,387.36 5368.05,436.57 ; U614.5@5390.99,390.39 5368.05,436.57 ; T600.20@5418.95,674.19 5406.05,652.01 ; T600.20@5423.05,671.23 5406.05,652.01 ; T600.20@5423.05,705.48 5423.05,669.01 5406.05,652.01 ; T600.20@5426.49,667.52 5406.05,652.01
GP6_GE_2_4-ETHERNET: T601.17 U615.6 | length 1067.8
  Top w8: T601.17@6044,679.25 6029.05,655.01 ; T601.17@6048.05,676.23 6029.05,655.01 ; T601.17@6048.05,710.48 6048.05,674.01 6029.05,655.01 ; T601.17@6051.5,672.54 6029.05,655.01 ; U615.6@6170.01,485.08 6192.05,438.44 ; U615.6@6177.63,487.96 6192.05,438.44 ; U615.6@6185.5,489.6 6192.05,438.44 ; U615.6@6200.58,489.31 6192.05,438.44 ; U615.6@6208.38,487.37 6192.05,438.44 ; U615.6@6215.88,484.19 6192.05,438.44 ; 6029.05,655.01 6029.05,554.01 6050.05,533.01 6050.05,466.01 6084.05,432.01 6084.05,372.01 6113.05,343.01 6166.05,343.01 6192.05,369.01 6192.05,489.01 U615.6@6193.05,490.01 6192.05,438.44
GP6_GE_4-ETHERNET: T600.17 U614.6 | length 1067.8
  Top w8: T600.17@5269,674.25 5254.05,650.01 ; T600.17@5273.05,671.23 5254.05,650.01 ; T600.17@5273.05,705.48 5273.05,669.01 5254.05,650.01 ; T600.17@5276.5,667.54 5254.05,650.01 ; U614.6@5395.01,480.08 5417.05,433.44 ; U614.6@5402.63,482.96 5417.05,433.44 ; U614.6@5410.5,484.6 5417.05,433.44 ; U614.6@5425.58,484.31 5417.05,433.44 ; U614.6@5433.38,482.37 5417.05,433.44 ; U614.6@5440.88,479.19 5417.05,433.44 ; 5254.05,650.01 5254.05,549.01 5275.05,528.01 5275.05,461.01 5309.05,427.01 5309.05,367.01 5338.05,338.01 5391.05,338.01 5417.05,364.01 5417.05,484.01 U614.6@5418.05,485.01 5417.05,433.44
GP7_GE_2_4-ETHERNET: T601.22 U615.7 | length 803.5
  Top w8: U615.7@6220.7,397.46 6248.05,442.29 ; U615.7@6227.95,393.77 6248.05,442.29 ; U615.7@6235.6,391.27 6248.05,442.29 ; U615.7@6250.61,389.83 6248.05,442.29 ; U615.7@6258.59,390.84 6248.05,442.29 ; U615.7@6266.41,393.08 6248.05,442.29 ; T601.22@6295.04,672.17 6317.05,659.01 ; T601.22@6298.05,676.23 6317.05,659.01 ; T601.22@6298.05,710.48 6298.05,678.01 6317.05,659.01 ; T601.22@6301.8,679.62 6317.05,659.01 ; 6248.05,442.29 U615.7@6243.05,390.01 6243.05,402.01 6248.05,407.01 6248.05,523.01 6317.05,592.01 6317.05,659.01
GP7_GE_4-ETHERNET: T600.22 U614.7 | length 803.5
  Top w8: U614.7@5445.7,392.46 5473.05,437.29 ; U614.7@5452.95,388.77 5473.05,437.29 ; U614.7@5460.6,386.27 5473.05,437.29 ; U614.7@5475.61,384.83 5473.05,437.29 ; U614.7@5483.59,385.84 5473.05,437.29 ; U614.7@5491.41,388.08 5473.05,437.29 ; T600.22@5520.04,667.17 5542.05,654.01 ; T600.22@5523.05,671.23 5542.05,654.01 ; T600.22@5523.05,705.48 5523.05,673.01 5542.05,654.01 ; T600.22@5526.8,674.62 5542.05,654.01 ; 5473.05,437.29 U614.7@5468.05,385.01 5468.05,397.01 5473.05,402.01 5473.05,518.01 5542.05,587.01 5542.05,654.01
GP8_GE_2_4-ETHERNET: T601.23 U615.8 | length 585.3
  Top w8: U615.8@6280.08,470.35 6261.05,497.01 ; U615.8@6286.21,476.03 6261.05,497.01 ; U615.8@6289.47,513.3 6261.05,497.01 ; U615.8@6290.59,482.86 6261.05,497.01 ; U615.8@6292.67,505.56 6261.05,497.01 ; U615.8@6293.8,497.53 6261.05,497.01 ; T601.23@6344.39,679.72 6330.05,661.01 ; T601.23@6348.05,676.23 6330.05,661.01 ; T601.23@6348.05,710.48 6349.05,709.48 6349.05,680.01 6330.05,661.01 ; T601.23@6350.88,672.04 6330.05,661.01 ; 6261.05,497.01 6268.05,490.01 U615.8@6293.05,490.01 6261.05,497.01 ; 6261.05,497.01 6261.05,517.01 6330.05,586.01 6330.05,661.01
GP8_GE_4-ETHERNET: T600.23 U614.8 | length 585.3
  Top w8: U614.8@5505.08,465.35 5486.05,492.01 ; U614.8@5511.21,471.03 5486.05,492.01 ; U614.8@5514.47,508.3 5486.05,492.01 ; U614.8@5515.59,477.86 5486.05,492.01 ; U614.8@5517.67,500.56 5486.05,492.01 ; U614.8@5518.8,492.53 5486.05,492.01 ; T600.23@5569.39,674.72 5555.05,656.01 ; T600.23@5573.05,671.23 5555.05,656.01 ; T600.23@5573.05,705.48 5574.05,704.48 5574.05,675.01 5555.05,656.01 ; T600.23@5575.88,667.04 5555.05,656.01 ; 5486.05,492.01 5486.05,512.01 5555.05,581.01 5555.05,656.01 ; 5486.05,492.01 5493.05,485.01 U614.8@5518.05,485.01 5486.05,492.01
GPHY_RESET_1-CPU-RT0: R716.1 RC2.1 U607.35 | length 572.5
  Top w8: U607.35@4539.26,2007.28 4539.26,2028.05 ; U607.35@4539.26,2018.11 4539.26,2028.05 ; R716.1@4602.49,2098.96 4579.69,2068.48 ; R716.1@4610.83,2090.38 4579.69,2068.48 ; 4539.26,2028.05 4606.21,2095 R716.1@4607,2095 4579.69,2068.48
  Top w12: RC2.1@4615,2135.41 4608.62,2135.41 RC2.1@4606.21,2133 ; R716.1@4606.21,2095 R716.1@4607,2095 ; R716.1@4606.21,2095 RC2.1@4606.21,2133 ; R716.1@4606.21,2095 4620.72,2133.32 R716.1@4607,2095 ; R716.1@4606.21,2095 4605.02,2135.96 R716.1@4607,2095 ; R716.1@4606.21,2095 4613,2135.41 R716.1@4607,2095 ; RC2.1@4606.21,2133 R716.1@4607,2095
GPIO0: R124.2 R126.2 U1.D7 | length 3352
  Top w4.5: U1.D7@2627.29,2306.67 U1.D7@2627.5,2306.65 ; v1(3245,3310) 3270,3310 ; v1@3245.21,3306.76 3270,3310 ; v1@3245.21,3313.24 3270,3310 ; v1@3246.2,3302.34 3270,3310 ; v1@3246.2,3317.66 3270,3310 ; R124.2@3310.27,3524.43 3315.85,3501.55 ; R124.2@3310.25,3525.23 3313.41,3501.41 ; R126.2@3310.31,3490.95 3317,3513.53 ; R124.2@3310.31,3524.05 3317,3501.47 ; R124.2@3310.3,3524.14 R126.2@3318,3490 ; R124.2@3310.41,3523.43 R126.2@3321.23,3490.36 ; R124.2@3310.68,3522.46 R126.2@3324.61,3494.09 ; R126.2@3313.59,3483.62 3330,3477 ; R126.2@3314.75,3490.09 3317,3513.53 ; R124.2@3314.75,3524.85 R126.2@3318,3490 ; R124.2@3314.75,3524.91 3317,3501.47 ; R124.2@3314.75,3525.07 3315.85,3501.55 ; R124.2@3314.77,3525.4 3313.41,3501.41 ; R124.2@3314.78,3524.55 R126.2@3321.23,3490.36 ; R124.2@3314.86,3524.16 R126.2@3324.61,3494.09 ; R126.2@3315.82,3487.59 3330,3477 ; R126.2@3320.58,3491.98 3330,3477 ; R124.2@3321.14,3524.16 3313.41,3501.41 ; R124.2@3321.21,3524.48 3315.85,3501.55 ; R124.2@3321.21,3525.52 R126.2@3324.61,3494.09 ; R124.2@3321.23,3524.64 3317,3501.47 ; R124.2@3321.25,3524.85 R126.2@3318,3490 ; R124.2@3321.25,3525.15 R126.2@3321.23,3490.36 ; R126.2@3324.71,3493.88 3330,3477 ; R124.2@3325.27,3522.31 3313.41,3501.41 ; R124.2@3325.5,3523.03 3315.85,3501.55 ; R126.2@3325.58,3491.6 3317,3513.53 ; R124.2@3325.58,3523.4 3317,3501.47 ; R124.2@3325.7,3524.14 R126.2@3318,3490 ; R124.2@3325.72,3525.68 R126.2@3324.61,3494.09 ; R124.2@3325.75,3524.86 R126.2@3321.23,3490.36 ; 3270,3310 3330,3370 3330,3477 ; R124.2@3310.5,3523.04 3317,3513.53 ; R124.2@3310.5,3523.04 3317,3513.53 ; R124.2@3310.5,3523.04 3317,3513.53 ; R124.2@3310.5,3523.04 3317,3513.53 ; R124.2@3310.5,3523.04 3317,3513.53 ; 3313.41,3501.41 R124.2@3318,3525 ; R124.2@3314.75,3524.82 3317,3513.53 ; R124.2@3314.75,3524.82 3317,3513.53 ; R124.2@3314.75,3524.82 3317,3513.53 ; R124.2@3314.75,3524.82 3317,3513.53 ; R124.2@3314.75,3524.82 3317,3513.53 ; 3315.85,3501.55 R124.2@3318,3525 ; 3317,3501.47 R124.2@3318,3525 ; 3317,3513.53 R126.2@3321.23,3490.36 ; 3317,3513.53 R126.2@3318,3490 ; 3317,3513.53 R124.2@3325.04,3521.77 ; 3317,3513.53 R124.2@3321.17,3524.26 ; 3317,3513.53 R124.2@3318,3525 ; 3317,3513.53 R124.2@3325.04,3521.77 ; 3317,3513.53 R124.2@3321.17,3524.26 ; 3317,3513.53 R124.2@3318,3525 ; 3317,3513.53 R124.2@3325.04,3521.77 ; 3317,3513.53 R124.2@3321.17,3524.26 ; 3317,3513.53 R124.2@3318,3525 ; 3317,3513.53 R124.2@3325.04,3521.77 ; 3317,3513.53 R124.2@3321.17,3524.26 ; 3317,3513.53 R124.2@3318,3525 ; 3317,3513.53 R124.2@3325.04,3521.77 ; 3317,3513.53 R124.2@3321.17,3524.26 ; 3317,3513.53 R124.2@3318,3525 ; R126.2@3318,3490 3330,3477 ; R126.2@3318,3490 R124.2@3318,3525 ; R124.2@3318,3525 3317,3525 3317,3490 3330,3477 ; R124.2@3318,3525 R126.2@3324.61,3494.09 ; R124.2@3318,3525 R126.2@3321.23,3490.36
  Top w5: R126.2@3317,3490 R126.2@3318,3490
  Top w8: U1.D7@2627.5,2306.65 v2(2627.5,2290.5) ; v2(2627.5,2290.5) U1.D7@2627.29,2306.67 v2(2627.5,2290.5)
  Inner Layer 3 w4.5: v2(2627.5,2290.5) 2647.23,2290.5 ; v2@2628.34,2284.81 2647.23,2290.5 ; v2@2628.34,2296.19 2647.23,2290.5 ; v1@3242.03,3317.16 3215.61,3302 ; v1@3243.98,3313.09 3215.61,3302 ; v1@3245.69,3306.82 3215.61,3302 ; v1@3246.07,3302.32 3215.61,3302 ; 2647.23,2290.5 2648.38,2291.65 2702.39,2291.65 2778,2367.26 2778,2396.4 3040,2658.4 3040,3214.4 3075.6,3250 3113.28,3250 3165.28,3302 3237,3302 v1(3245,3310) 3215.61,3302
HOLD_2-MEMORY: R151.1 U18.7 | length 1465.6
  Top w4.5: U18.7@3164.69,4025.23 3180,4048.04 ; U18.7@3168.67,4023.01 3180,4048.04 ; U18.7@3175,4009.8 3175,4008 3180,4013 3180,4057 3183,4060 R151.1@3188,4060 ; U18.7@3175,4021.02 3180,4048.04 ; R151.1@3180.26,4059.6 U18.7@3186.13,4021.26 ; R151.1@3180.27,4060.49 U18.7@3181.62,4020.61 ; R151.1@3180.34,4061.2 U18.7@3180,4034.08 ; R151.1@3180.5,4061.97 3177.98,4037.15 ; R151.1@3180.76,4062.76 3175.59,4038.31 ; R151.1@3180.98,4063.29 3173.79,4038.78 ; R151.1@3184.75,4060.02 U18.7@3186.13,4021.26 ; R151.1@3184.77,4060.39 U18.7@3181.62,4020.61 ; R151.1@3184.84,4060.77 U18.7@3180,4034.08 ; R151.1@3184.94,4061.11 3177.98,4037.15 ; R151.1@3185.08,4061.43 3175.59,4038.31 ; R151.1@3185.19,4061.63 3173.79,4038.78 ; R151.1@3190.58,4058.02 3173.79,4038.78 ; R151.1@3190.71,4058.21 3175.59,4038.31 ; R151.1@3190.89,4058.5 3177.98,4037.15 ; R151.1@3191.04,4058.86 U18.7@3180,4034.08 ; R151.1@3191.18,4059.35 U18.7@3181.62,4020.61 ; R151.1@3191.24,4059.71 U18.7@3186.13,4021.26 ; R151.1@3193.71,4054.76 3173.79,4038.78 ; R151.1@3194.05,4055.16 3175.59,4038.31 ; R151.1@3194.53,4055.82 3177.98,4037.15 ; R151.1@3195,4056.68 U18.7@3180,4034.08 ; R151.1@3195.49,4058.02 U18.7@3181.62,4020.61 ; R151.1@3195.67,4058.86 U18.7@3186.13,4021.26 ; 3173.79,4038.78 R151.1@3188,4060 ; 3175.59,4038.31 R151.1@3188,4060 ; 3177.98,4037.15 R151.1@3188,4060 ; U18.7@3180,4034.08 R151.1@3188,4060 ; 3180,4048.04 U18.7@3186.13,4021.26 ; 3180,4048.04 U18.7@3181.62,4020.61 ; 3180,4048.04 R151.1@3193.04,4054.11 ; 3180,4048.04 R151.1@3180.64,4062.42 ; 3180,4048.04 R151.1@3190.48,4057.9 ; 3180,4048.04 R151.1@3185.11,4061.49 ; 3180,4048.04 R151.1@3188,4060 ; 3180,4048.04 R151.1@3193.04,4054.11 ; 3180,4048.04 R151.1@3180.64,4062.42 ; 3180,4048.04 R151.1@3190.48,4057.9 ; 3180,4048.04 R151.1@3185.11,4061.49 ; 3180,4048.04 R151.1@3188,4060 ; 3180,4048.04 R151.1@3193.04,4054.11 ; 3180,4048.04 R151.1@3180.64,4062.42 ; 3180,4048.04 R151.1@3190.48,4057.9 ; 3180,4048.04 R151.1@3185.11,4061.49 ; 3180,4048.04 R151.1@3188,4060 ; 3180,4048.04 R151.1@3193.04,4054.11 ; 3180,4048.04 R151.1@3180.64,4062.42 ; 3180,4048.04 R151.1@3190.48,4057.9 ; 3180,4048.04 R151.1@3185.11,4061.49 ; 3180,4048.04 R151.1@3188,4060 ; 3180,4048.04 R151.1@3193.04,4054.11 ; 3180,4048.04 R151.1@3180.64,4062.42 ; 3180,4048.04 R151.1@3190.48,4057.9 ; 3180,4048.04 R151.1@3185.11,4061.49 ; 3180,4048.04 R151.1@3188,4060 ; U18.7@3181.62,4020.61 R151.1@3188,4060 ; U18.7@3186.13,4021.26 R151.1@3188,4060
I2C_SCLK_1-CPU-RT0: R53.2 R808.2 U1.U14 U9.6 | length 7296.2
  Top w4.5: R808.2@304.98,3070.36 v1@312.81,3045.19 ; v1@305.35,3043.79 R808.2@305.14,3069.87 ; v1@305.67,3042.49 R808.2@300.8,3068.66 ; v1@306.03,3041.61 R808.2@298,3067 ; v1@306.49,3040.79 R808.2@295.43,3065.01 ; v1@306.61,3040.61 R808.2@298,3060 ; v1@307.3,3039.75 R808.2@292.3,3061.75 ; v1@309.85,3044.22 R808.2@305.14,3069.87 ; v1@310.03,3043.69 R808.2@300.8,3068.66 ; v1@310.21,3043.34 R808.2@298,3067 ; v1@310.43,3043.01 R808.2@295.43,3065.01 ; v1@310.53,3042.88 R808.2@298,3060 ; v1@310.81,3042.6 R808.2@292.3,3061.75 ; v1@314.89,3047.65 R808.2@292.3,3061.75 ; v1@315.12,3047.47 R808.2@298,3060 ; v1@315.31,3047.29 R808.2@295.43,3065.01 ; v1@315.57,3046.99 R808.2@298,3067 ; v1@315.79,3046.66 R808.2@300.8,3068.66 ; v1@316.03,3046.17 R808.2@305.14,3069.87 ; v1@316.95,3051.67 R808.2@292.3,3061.75 ; v1@317.39,3051.39 R808.2@298,3060 ; v1@318.02,3050.91 R808.2@295.43,3065.01 ; v1@318.7,3050.25 R808.2@298,3067 ; v1@319.3,3049.52 R808.2@300.8,3068.66 ; v1@319.96,3048.41 R808.2@305.14,3069.87 ; U9.6@650.35,1053.87 674.44,1076.44 ; U9.6@653.66,1050.79 674.44,1076.44 ; U9.6@658,1035.51 658,1060 ; U9.6@662.75,1045.57 674.44,1076.44 ; U9.6@667.09,1044.26 674.44,1076.44 ; v1@674.55,1087.15 670.39,1058.72 ; v1@674.77,1087.79 668.3,1060.22 ; v1@675.07,1088.47 666,1061.75 ; v1@675.45,1089.14 663.31,1062.7 ; v1@675.75,1089.58 661.19,1063.19 ; v1@675.85,1089.72 660.58,1063.45 ; v1@678.96,1086.14 670.39,1058.72 ; v1@679.07,1086.41 668.3,1060.22 ; v1@679.22,1086.69 666,1061.75 ; v1@679.4,1086.95 663.31,1062.7 ; v1@679.53,1087.11 661.19,1063.19 ; v1@679.58,1087.17 660.58,1063.45 ; v1@682.21,1081.76 707.5,1085 ; v1@682.21,1088.24 707.5,1085 ; v1@683.18,1077.34 707.5,1085 ; v1@683.18,1092.66 707.5,1085 ; v1@684.18,1082.59 660.58,1063.45 ; v1@684.23,1082.63 661.19,1063.19 ; v1@684.37,1082.78 663.31,1062.7 ; v1@684.57,1083.01 666,1061.75 ; v1@684.75,1083.27 668.3,1060.22 ; v1@684.89,1083.52 670.39,1058.72 ; v1@686.75,1078.88 660.58,1063.45 ; v1@686.87,1078.97 661.19,1063.19 ; v1@687.22,1079.28 663.31,1062.7 ; v1@687.72,1079.77 666,1061.75 ; v1@688.21,1080.36 668.3,1060.22 ; v1@688.6,1080.94 670.39,1058.72 ; R53.2@748.45,1050.86 737.37,1075.63 ; R53.2@750.51,1061.32 774.86,1073.86 ; R53.2@752.41,1053.04 737.37,1075.63 ; R53.2@752.91,1057.49 774.86,1073.86 ; R53.2@757.37,1052.78 774.86,1073.86 ; R53.2@757.34,1057.26 737.37,1075.63 ; R53.2@760.11,1060.82 737.37,1075.63 ; R53.2@761.08,1050.19 774.86,1073.86 ; U1.U14@2515.93,1947.13 2504.81,1931.22 ; U1.U14@2521.01,1941.91 2504.81,1931.22 ; R808.2@292.3,3061.75 v1@312.81,3045.19 ; R808.2@292.3,3061.75 v1(313,3045) ; R808.2@295.43,3065.01 v1@312.81,3045.19 ; R808.2@295.43,3065.01 v1(313,3045) ; R808.2@298,3060 v1(313,3045) ; R808.2@298,3060 R808.2@298,3067 ; R808.2@298,3060 v1(313,3045) ; R808.2@298,3067 v1@312.81,3045.19 ; R808.2@298,3067 v1(313,3045) ; R808.2@300.8,3068.66 v1@312.81,3045.19 ; R808.2@300.8,3068.66 v1(313,3045) ; R808.2@305.14,3069.87 v1(313,3045) ; U9.6@658,1047.82 658,1060 ; U9.6@658,1047.82 674.44,1076.44 ; U9.6@658,1047.82 658,1060 ; 658,1060 682,1084 v1(682,1085) ; 658,1060 649.06,1051.72 658,1060 ; 658,1060 666.94,1051.72 658,1060 ; 658,1060 652.87,1048.95 658,1060 ; 658,1060 663.13,1048.95 658,1060 ; 660.58,1063.45 v1(682,1085) ; 661.19,1063.19 v1(682,1085) ; 663.31,1062.7 v1(682,1085) ; 666,1061.75 v1(682,1085) ; 668.3,1060.22 v1(682,1085) ; 670.39,1058.72 v1(682,1085) ; v1(682,1085) 728,1085 753,1060 753,1058 R53.2@756,1055 ; 737.37,1075.63 R53.2@755,1055 ; R53.2@755,1055 R53.2@756,1055 ; R53.2@755,1055 774.86,1073.86 ; R53.2@756,1055 781,1080 878,1080 893,1095 893,1182.73 1208.27,1498 2146,1498 2460,1812 2460,1886.41 2518.53,1944.94 U1.U14@2518.71,1944.76 2504.81,1931.22
  Bottom w4.5: v1@308.26,3038.87 334.55,3023.45 ; v1@310.83,3042.58 334.55,3023.45 ; v1(313,3045) 690,2668 690,1093 v1(682,1085) 690,1115.39 ; v1@315.42,3047.17 334.55,3023.45 ; v1@319.13,3049.74 334.55,3023.45 ; v1@674.81,1087.88 690,1115.39 ; v1@678.9,1085.99 690,1115.39 ; v1@685.18,1084.34 690,1115.39 ; v1@689.68,1083.97 690,1115.39
I2C_SD_1-CPU-RT0: R52.2 R809.2 U1.T14 U9.5 | length 3099.2
  Top w4.5: U9.5@704.87,1026.27 738.65,1020 ; U9.5@705.99,1030.65 738.65,1020 ; U9.5@710.73,1040.01 738.65,1020 ; U9.5@713.6,1043.5 738.65,1020 ; R52.2@760.51,1013.68 784.83,1001.17 ; R52.2@762.91,1017.51 784.83,1001.17 ; R52.2@763.72,1012.36 741.5,1020 ; R52.2@763.72,1027.64 741.5,1020 ; R52.2@764.78,1016.76 741.5,1020 ; R52.2@764.78,1023.24 741.5,1020 ; R52.2@767.37,1022.22 784.83,1001.17 ; R52.2@771.08,1024.81 784.83,1001.17 ; R809.2@911.28,1174.66 913,1149.32 ; R809.2@912.8,1178.65 934.05,1200.55 ; R809.2@915.8,1174.56 913,1149.32 ; R809.2@916.26,1175.75 934.05,1200.55 ; R809.2@921.91,1172.55 934.05,1200.55 ; R809.2@922.1,1173.03 913,1149.32 ; U1.T14@2533.17,1962.48 2536.81,1944.96 ; U1.T14@2540.45,1962.48 2536.81,1944.96 ; 738.65,1020 U9.5@708,1035.51 708,1020 R52.2@765,1020 ; R52.2@765,1020 766,1020 788,998 816,998 913,1095 R809.2@913,1175 ; R52.2@765,1020 784.83,1001.17 ; 913,1149.32 926.16,1171.04 934.05,1200.55 ; 913,1149.32 R809.2@919,1174 ; R809.2@913,1175 919,1175 920,1174 R809.2@919,1174 ; R809.2@913,1175 913,1179.5 1221.5,1488 2151,1488 2470,1807 2470,1878.15 2523.85,1932 2523.92,1931.92 2536.88,1944.88 2536.81,1944.96 ; R809.2@919,1174 934.05,1200.55 ; 2536.81,1944.96 U1.T14@2536.81,1962.86 2536.81,1944.96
